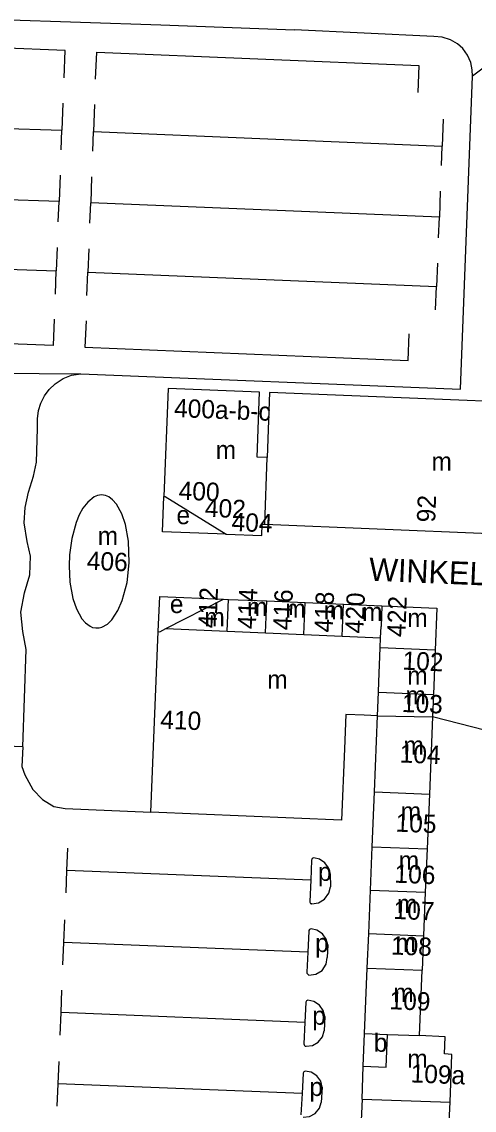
# Model space of a CAD drawing. Extents: x 159675 to 162108, y 386471 to 388472.
# Drawn here: x 161036.8 to 161135.6, y 386600.8 to 386838.6 of the extents above; entities that cross this region are included whole.
import ezdxf

# ---------------------------------------------------------------- set-up
doc = ezdxf.new("R2010")
doc.units = 0
for name, color, linetype in [('BLT_Basislijn', 7, 'Continuous'), ('BLT_Bebouwing', 7, 'Continuous'), ('BLT_Centroide', 7, 'Continuous'), ('BLT_Huisnummer', 7, 'Continuous'), ('BLT_Huisnummer_reeks', 7, 'Continuous'), ('BLT_Onderverdeling_panden', 7, 'Continuous'), ('BLT_Straatnaam', 7, 'Continuous'), ('BLT_Vlakafsluiter', 7, 'Continuous')]:
    doc.layers.add(name, color=color, linetype=linetype)

msp = doc.modelspace()

# ---------------------------------------------------------------- linework, layer by layer
at = {"layer": 'BLT_Basislijn'}
for p, q in [((161045.81, 386820.83), (161045.56, 386814.95)), ((161052.7, 386820.53), (161052.45, 386814.64)), ((160965.51, 386817.25), (161045.56, 386814.95)), ((161128.84, 386817.36), (161128.59, 386811.47)), ((161045.42, 386810.65), (161045.56, 386814.95)), ((161052.31, 386810.35), (161052.45, 386814.64)), ((161052.45, 386814.64), (161128.59, 386811.47)), ((161128.45, 386807.18), (161128.59, 386811.47)), ((161045.17, 386805.07), (161044.98, 386799.38)), ((161052.06, 386804.77), (161051.87, 386799.07)), ((161044.98, 386799.38), (160964.93, 386801.68)), ((161128.2, 386801.6), (161128.01, 386795.9)), ((161044.77, 386794.9), (161044.98, 386799.38)), ((161051.66, 386794.6), (161051.87, 386799.07)), ((161128.01, 386795.9), (161051.87, 386799.07)), ((161127.8, 386791.43), (161128.01, 386795.9)), ((161044.55, 386789.33), (161044.35, 386784.23)), ((161051.44, 386789.03), (161051.24, 386783.93)), ((160964.3, 386786.54), (161044.35, 386784.23)), ((161127.58, 386785.86), (161127.38, 386780.76)), ((161044.16, 386779.13), (161044.35, 386784.23)), ((161051.05, 386778.83), (161051.24, 386783.93)), ((161051.24, 386783.93), (161127.38, 386780.76)), ((161127.19, 386775.66), (161127.38, 386780.76)), ((161046.68, 386653.21), (161046.87, 386658.1)), ((161046.49, 386648.32), (161046.68, 386653.21)), ((161099.91, 386651.09), (161046.68, 386653.21)), ((161046, 386637.49), (161046.19, 386642.38)), ((161045.81, 386632.59), (161046, 386637.49)), ((161099.26, 386635.37), (161046, 386637.49)), ((161045.39, 386622.14), (161045.58, 386627.03)), ((161045.2, 386617.24), (161045.39, 386622.14)), ((161098.65, 386620.02), (161045.39, 386622.14)), ((161044.76, 386606.58), (161044.95, 386611.47)), ((161044.57, 386601.69), (161044.76, 386606.58)), ((161098.01, 386604.46), (161044.76, 386606.58))]:
    msp.add_line(p, q, dxfattribs=at)
for points in [[(160969.98, 386847), (161032.1, 386844.2), (161032.1, 386839.13), (161067.18, 386837.96), (161096.34, 386836.86)], [(161046.04, 386826.36), (161046.26, 386832.33), (160973.8, 386835.27), (160973.55, 386829.3)], [(161135.2, 386826.74), (161135.17, 386828.14), (161134.84, 386829.73), (161134.14, 386831.33), (161133.11, 386832.74), (161131.93, 386833.81), (161130.45, 386834.69), (161128.64, 386835.26), (161126.8, 386835.41), (161096.34, 386836.86)], [(161052.92, 386826.09), (161053.18, 386831.99), (161123.52, 386829.08), (161123.28, 386823.19)], [(161049.71, 386761.68), (161132.59, 386758.36), (161135.2, 386826.74)], [(161043.91, 386773.63), (161043.68, 386767.9), (160971.29, 386770.67), (160971.52, 386776.56)], [(161050.85, 386773.31), (161050.6, 386767.49), (161121.17, 386764.6), (161121.41, 386770.44)], [(161037.04, 386680.24), (161037.76, 386701.5), (161037.04, 386705.39), (161036.59, 386709.64), (161037.39, 386713.84), (161038.55, 386717.77), (161038.7, 386721.87), (161038.02, 386725.04), (161037.35, 386729.13), (161037.54, 386732.53), (161038.3, 386735.86), (161039.39, 386739.32), (161040.01, 386742.43), (161040.23, 386749.77), (161040.28, 386751.85), (161040.49, 386753.67), (161040.97, 386755.3), (161041.76, 386756.88), (161042.83, 386758.3), (161044.14, 386759.5), (161045.85, 386760.7), (161047.67, 386761.41), (161049.71, 386761.68)], [(161081.42, 386726.66), (161067.51, 386727.19), (161067.82, 386734.91)], [(161066.62, 386705.37), (161066.94, 386713.06), (161080.85, 386712.48)], [(161037.04, 386680.24), (161036.85, 386675.88), (161037.47, 386674.07), (161039.23, 386670.89), (161041.32, 386668.69), (161043.8, 386667.16), (161046.3, 386666.72), (161064.98, 386665.92)], [(161100.11, 386655.44), (161099.91, 386651.09)], [(161100.59, 386655.97), (161100.4, 386655.92), (161100.24, 386655.8), (161100.14, 386655.62), (161100.11, 386655.44)], [(161104.18, 386652.49), (161103.82, 386653.75), (161103.01, 386654.88), (161101.86, 386655.66), (161100.59, 386655.97)], [(161104.18, 386652.49), (161104.21, 386649.62)], [(161099.91, 386651.09), (161099.71, 386646.42)], [(161100.16, 386645.92), (161101.59, 386646.14), (161102.94, 386646.94), (161103.86, 386648.21), (161104.21, 386649.62)], [(161099.71, 386646.42), (161099.69, 386646.27), (161099.75, 386646.11), (161099.86, 386645.99), (161100, 386645.92)], [(161100.16, 386645.92), (161100, 386645.92)], [(161099.98, 386640.43), (161099.79, 386640.4), (161099.62, 386640.29), (161099.5, 386640.12), (161099.46, 386639.94)], [(161103.62, 386636.92), (161103.27, 386638.2), (161102.45, 386639.36), (161101.27, 386640.13), (161099.98, 386640.43)], [(161099.46, 386639.94), (161099.26, 386635.37)], [(161099.26, 386635.37), (161099.06, 386630.98)], [(161103.62, 386636.92), (161103.49, 386634.2)], [(161099.51, 386630.36), (161100.99, 386630.52), (161102.39, 386631.36), (161103.28, 386632.73), (161103.49, 386634.2)], [(161099.06, 386630.98), (161099.08, 386630.78), (161099.18, 386630.59), (161099.33, 386630.44), (161099.51, 386630.36)], [(161098.86, 386624.43), (161098.65, 386620.02)], [(161099.29, 386624.86), (161099.14, 386624.81), (161099.01, 386624.71), (161098.91, 386624.58), (161098.86, 386624.43)], [(161103.01, 386621.32), (161102.66, 386622.62), (161101.82, 386623.8), (161100.61, 386624.58), (161099.29, 386624.86)], [(161103.01, 386621.32), (161102.84, 386618.15)], [(161098.65, 386620.02), (161098.43, 386615.31)], [(161098.93, 386614.78), (161100.28, 386614.98), (161101.55, 386615.7), (161102.45, 386616.85), (161102.84, 386618.15)], [(161098.43, 386615.31), (161098.44, 386615.13), (161098.52, 386614.97), (161098.66, 386614.84), (161098.82, 386614.79)], [(161098.82, 386614.79), (161098.93, 386614.78)], [(161098.73, 386609.34), (161098.57, 386609.3), (161098.42, 386609.21), (161098.3, 386609.08), (161098.23, 386608.93)], [(161102.39, 386605.88), (161102.09, 386607.18), (161101.26, 386608.36), (161100.04, 386609.12), (161098.73, 386609.34)], [(161098.23, 386608.93), (161098.01, 386604.46)], [(161098.01, 386604.46), (161097.77, 386599.84)], [(161102.39, 386605.88), (161102.21, 386602.54)], [(161098.28, 386599.28), (161099.62, 386599.44), (161100.89, 386600.14), (161101.8, 386601.26), (161102.21, 386602.54)]]:
    msp.add_lwpolyline(points, dxfattribs=at)
at = {"layer": 'BLT_Bebouwing'}
for p, q in [((161064.98, 386665.92), (161066.62, 386705.37)), ((161127.09, 386701.35), (161126.69, 386691.65)), ((161126.69, 386691.65), (161126.5, 386686.79)), ((161113.81, 386670.36), (161114.47, 386686.99)), ((161126.5, 386686.79), (161125.81, 386669.89)), ((161113.32, 386658.37), (161113.81, 386670.36)), ((161125.81, 386669.89), (161125.32, 386657.89)), ((161106.62, 386664.18), (161064.98, 386665.92)), ((161112.94, 386648.91), (161113.32, 386658.37)), ((161125.32, 386657.89), (161124.93, 386648.43)), ((161112.56, 386639.4), (161112.94, 386648.91)), ((161124.93, 386648.43), (161124.54, 386638.92)), ((161112.26, 386631.87), (161112.56, 386639.4)), ((161124.54, 386638.92), (161124.24, 386631.39)), ((161111.11, 386603.27), (161110.62, 386591.18)), ((161129.82, 386590.42), (161130.32, 386602.57))]:
    msp.add_line(p, q, dxfattribs=at)
for points in [[(161090.43, 386743.4), (161088.24, 386743.49), (161088.74, 386757.7), (161068.76, 386758.51), (161067.82, 386734.91)], [(161090.94, 386757.6), (161090.43, 386743.4)], [(161162.81, 386754.7), (161090.94, 386757.6)], [(161089.89, 386728.83), (161138.98, 386726.81), (161138.89, 386724.45), (161161.55, 386723.52), (161162.81, 386754.7)], [(161067.82, 386734.91), (161068.13, 386734.9), (161081.42, 386726.66)], [(161081.42, 386726.66), (161089.22, 386726.35), (161089.34, 386728.86), (161089.89, 386728.83)], [(161068.25, 386706.03), (161080.85, 386712.48)], [(161080.85, 386712.48), (161081.96, 386712.43)], [(161081.96, 386712.43), (161090.34, 386712.07)], [(161090.34, 386712.07), (161098.71, 386711.72)], [(161098.71, 386711.72), (161107.08, 386711.36)], [(161107.08, 386711.36), (161115.45, 386711.01)], [(161115.45, 386711.01), (161127.46, 386710.5), (161127.09, 386701.35)], [(161066.62, 386705.37), (161066.93, 386705.36), (161068.25, 386706.03)], [(161111.6, 386687.11), (161107.59, 386687.27), (161107.27, 386679.77), (161106.62, 386664.18)], [(161114.47, 386686.99), (161111.6, 386687.11)], [(161111.68, 386617.6), (161112.26, 386631.87)], [(161123.67, 386617.13), (161124.24, 386631.39)], [(161111.39, 386610.43), (161111.68, 386617.6)], [(161130.32, 386602.57), (161130.74, 386613.03), (161129.1, 386613.11), (161129.24, 386616.89), (161123.67, 386617.13)], [(161111.11, 386603.27), (161111.39, 386610.43)]]:
    msp.add_lwpolyline(points, dxfattribs=at)
msp.add_lwpolyline([(161048.68, 386729.22), (161047.72, 386725.73), (161047.22, 386722.15), (161047.13, 386719.78), (161047.34, 386716.18), (161047.99, 386712.64), (161048.77, 386710.33), (161049.94, 386708.19), (161050.74, 386707.28), (161051.72, 386706.55), (161052.29, 386706.31), (161052.99, 386706.18), (161053.7, 386706.18), (161054.31, 386706.33), (161055.5, 386707.02), (161056.5, 386707.97), (161057.82, 386709.98), (161058.77, 386712.2), (161059.79, 386716.12), (161060.28, 386720.43), (161060.11, 386725.15), (161059.44, 386728.77), (161058.67, 386731.1), (161057.47, 386733.26), (161056.66, 386734.17), (161055.84, 386734.8), (161055.07, 386735.12), (161054.23, 386735.24), (161053.35, 386735.12), (161052.62, 386734.83), (161051.27, 386733.68), (161050.16, 386732.37), (161049.31, 386730.91)], close=True, dxfattribs=at)
at = {"layer": 'BLT_Onderverdeling_panden'}
for p, q in [((161115.45, 386711.01), (161115.28, 386706.52)), ((161115.09, 386701.84), (161115.18, 386704.04)), ((161114.8, 386694.43), (161115.09, 386701.84)), ((161127.09, 386701.35), (161115.09, 386701.84)), ((161114.47, 386686.99), (161114.71, 386692.13)), ((161114.71, 386692.13), (161126.69, 386691.65)), ((161114.47, 386686.99), (161126.5, 386686.79)), ((161113.81, 386670.36), (161125.81, 386669.89)), ((161113.32, 386658.37), (161125.32, 386657.89)), ((161112.94, 386648.91), (161124.93, 386648.43)), ((161112.56, 386639.4), (161124.54, 386638.92)), ((161112.26, 386631.87), (161124.24, 386631.39)), ((161111.68, 386617.6), (161116.67, 386617.4)), ((161116.39, 386610.24), (161116.67, 386617.4)), ((161116.67, 386617.4), (161123.67, 386617.12)), ((161111.39, 386610.43), (161116.39, 386610.24)), ((161111.11, 386603.27), (161130.32, 386602.57))]:
    msp.add_line(p, q, dxfattribs=at)
for points in [[(161089.89, 386728.83), (161090.43, 386743.4)], [(161081.69, 386705.46), (161081.96, 386712.43)], [(161090.06, 386705.11), (161090.34, 386712.07)], [(161098.43, 386704.75), (161098.71, 386711.72)], [(161106.8, 386704.4), (161107.08, 386711.36)], [(161068.25, 386706.03), (161081.69, 386705.46)], [(161081.69, 386705.46), (161090.06, 386705.11)], [(161090.06, 386705.11), (161098.43, 386704.75)], [(161098.43, 386704.75), (161106.8, 386704.4)], [(161106.8, 386704.4), (161115.18, 386704.04)], [(161115.18, 386704.04), (161115.28, 386706.52)], [(161114.71, 386692.13), (161114.8, 386694.43)]]:
    msp.add_lwpolyline(points, dxfattribs=at)
at = {"layer": 'BLT_Vlakafsluiter'}
for p, q in [((161139.58, 386830), (161135.2, 386826.74)), ((161024.68, 386761.94), (161049.71, 386761.68)), ((161138.18, 386683.79), (161126.5, 386686.79)), ((161037.04, 386680.24), (161020.65, 386680.81))]:
    msp.add_line(p, q, dxfattribs=at)

# ---------------------------------------------------------------- texts
at = {"layer": 'BLT_Centroide'}
for s, p in [('m', (161079.16, 386743.08)), ('m', (161126.28, 386740.56)), ('e', (161070.59, 386728.85)), ('m', (161053.39, 386724.3)), ('e', (161069.15, 386709.43)), ('m', (161086.01, 386708.78)), ('m', (161094.38, 386708.41)), ('m', (161076.69, 386706.57)), ('m', (161102.76, 386708.06)), ('m', (161111.13, 386707.69)), ('m', (161121, 386706.4)), ('m', (161090.42, 386692.94)), ('m', (161121, 386693.79)), ('m', (161120.6, 386689.47)), ('m', (161120.16, 386678.52)), ('m', (161119.56, 386664.12)), ('m', (161119.13, 386653.41)), ('p', (161101.49, 386650.92)), ('m', (161118.74, 386643.91)), ('p', (161100.87, 386635.38)), ('m', (161118.41, 386635.41)), ('m', (161117.95, 386624.5)), ('p', (161100.24, 386619.49)), ('b', (161113.68, 386613.58)), ('m', (161121, 386610.09)), ('p', (161099.62, 386603.93))]:
    msp.add_text(s, height=4, dxfattribs=at).set_placement(p)
at = {"layer": 'BLT_Huisnummer'}
for s, rotation, p in [('406', 357.5724, (161050.95, 386718.92)), ('412', 87.7275, (161079.32, 386706.06)), ('414', 87.7275, (161087.91, 386705.88)), ('416', 87.7275, (161095.67, 386705.62)), ('418', 87.7275, (161104.68, 386705.13)), ('420', 87.7275, (161111.41, 386704.92)), ('422', 87.7275, (161120.54, 386704.14)), ('102', 357.3851, (161119.88, 386697.09)), ('103', 357.7151, (161119.75, 386687.83)), ('410', 357.6347, (161067, 386684.21)), ('104', 357.7151, (161119.27, 386676.8)), ('105', 357.7157, (161118.37, 386661.7)), ('106', 357.7149, (161118.14, 386650.54)), ('107', 357.7103, (161117.92, 386642.63)), ('108', 357.7102, (161117.36, 386634.86)), ('109', 357.7149, (161117.05, 386622.9)), ('109a', 357.7475, (161121.66, 386606.91))]:
    msp.add_text(s, height=4, rotation=rotation, dxfattribs=at).set_placement(p)
at = {"layer": 'BLT_Huisnummer_reeks'}
for s, rotation, p in [('400a-b-c', 357.6757, (161070.01, 386752.28)), ('400', 357.6757, (161071.01, 386734.23)), ('402', 357.6757, (161076.74, 386730.48)), ('92', 87.6817, (161127.06, 386729.18)), ('404', 357.6757, (161082.56, 386727.39))]:
    msp.add_text(s, height=4, rotation=rotation, dxfattribs=at).set_placement(p)
at = {"layer": 'BLT_Straatnaam'}
msp.add_text('WINKELCENTRUM WOENSEL', height=5, rotation=357.5852, dxfattribs=at).set_placement((161112.55, 386716.53))

doc.saveas('drawing.dxf')
